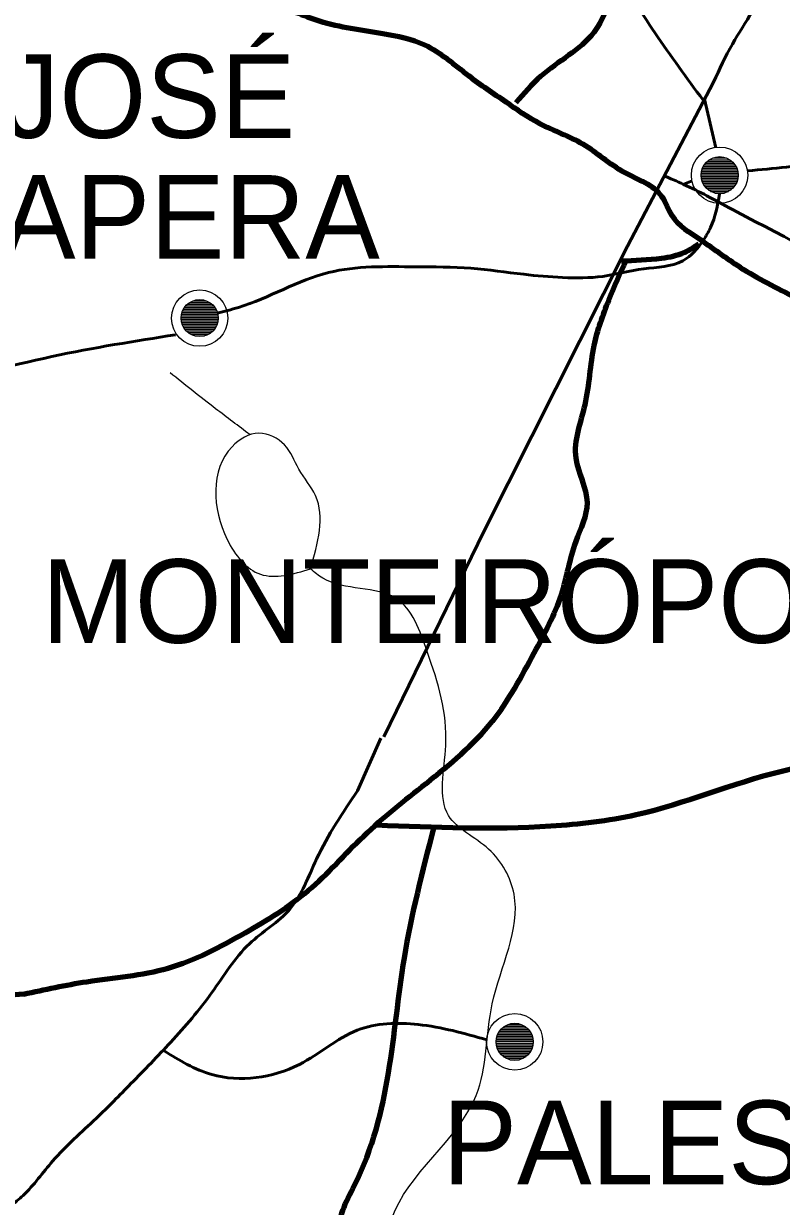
# Model space of a CAD drawing. Extents: x 512883 to 1063249, y 8784064 to 9081064.
# Drawn here: x 674490 to 688095, y 8927073 to 8948300 of the extents above; entities that cross this region are included whole.
import ezdxf

# ---------------------------------------------------------------- set-up
doc = ezdxf.new("R2010")
doc.units = 0
doc.header["$LTSCALE"] = 600
doc.linetypes.add('DOT_DASHED', pattern=[7.7, 5, -1.2, 0.3, -1.2])
for name, color, linetype, lineweight in [('10', 7, 'Continuous', 53), ('13', 7, 'Continuous', 90), ('3', 7, 'Continuous', 25), ('4', 7, 'Continuous', 13), ('5', 7, 'Continuous', 13)]:
    doc.layers.add(name, color=color, linetype=linetype, lineweight=lineweight)

msp = doc.modelspace()

# ---------------------------------------------------------------- linework, layer by layer
at = {"layer": '10'}
for p, q in [((686916.9, 8946073), (686716.2, 8946946.3)), ((686494.2, 8945478.8), (686344.1, 8945417.9)), ((680900.9, 8935478.2), (680484.1, 8934529.4))]:
    msp.add_line(p, q, dxfattribs=at)
msp.add_lwpolyline([(686879, 8947250.2), (685329.9, 8944307.9), (682756.7, 8939198.9), (680955.1, 8935497.3)], dxfattribs=at)
for points in [[(683363, 8951685.3), (684253.4, 8950848.9), (685091, 8949362.2), (685827.1, 8948131.8), (686690.1, 8946927.1)], [(686879, 8947250.2), (687215.3, 8947932.8), (687572, 8948527.5), (687786, 8948956.6), (688076.4, 8949437.6)], [(687492.6, 8945658.8), (688879.6, 8945806.7), (690884.8, 8946191.2), (692737.8, 8946575.7), (694590.7, 8946729.4), (697823.6, 8947505.2)], [(661143.8, 8945556.2), (662407.6, 8946035.8), (663719.6, 8946067.1), (664857.5, 8945518.9), (666015.1, 8944949.5), (668384.9, 8943538.4), (670469.7, 8942009.1), (674994.8, 8942323.4), (677217.8, 8942716)], [(690354.9, 8942526.3), (689817.4, 8943269.9), (687295.1, 8944922.2), (686757.6, 8945211.3), (686340.8, 8945414.9), (685973.5, 8945577)], [(677966.5, 8943105.4), (678346.6, 8943206.6), (679964.3, 8943832.1), (681523.6, 8943935.6), (682522.3, 8943909.7), (683470.1, 8943801.1), (684168.2, 8943744.2), (684886.6, 8943764.9), (685625.5, 8943899.4), (686323.6, 8944044.2), (686695.5, 8944416.5), (686822.9, 8944638.8), (686986.1, 8945247.1)], [(680484.1, 8934529.4), (679750.3, 8933309.1), (679271.3, 8932409.3), (678542.7, 8931783.6), (677870.1, 8930909.7), (677131.2, 8930020.3), (676417.8, 8929275.7), (675796.2, 8928655.1), (675011.5, 8927884.7), (674481.5, 8927269.3), (674252.2, 8927072.8)], [(677011.7, 8929863), (677867, 8929439.7), (679440.8, 8929619.1), (680481.5, 8930234.3), (681572.9, 8930336.8), (682804.7, 8930063.7)]]:
    msp.add_spline(points, degree=3, dxfattribs=at)
at = {"layer": '13'}
for points in [[(687717.5, 8953534.4), (685899.8, 8950515.2), (685172.7, 8949145.3), (684725.3, 8948138.9), (683774.5, 8947356.2), (683327, 8946880.9)], [(697917.7, 8940030.2), (695483.7, 8940642.8), (693475.6, 8941153.4), (692502.1, 8941214.7), (691508.2, 8941480.2), (690352, 8942072.5), (689439.3, 8942726), (688425.1, 8943338.7), (687411, 8943890.1), (686640.2, 8944421.1), (686133.1, 8944850), (685950.6, 8945197.2), (685281.2, 8945626.1), (684530.7, 8946136.7), (683760, 8946504.3), (683151.5, 8946892.3), (682482.1, 8947362.1), (681691.1, 8947913.5), (680940.6, 8948117.7), (679804.7, 8948342.4), (678932.6, 8948669.2), (678381, 8948825.9)], [(674490.5, 8930880.6), (672043.1, 8930925.7), (668845.2, 8932294), (665328.7, 8934774.4), (663896.9, 8936642.6), (661883.5, 8938670.4), (659757.9, 8940179.9), (657908.6, 8942328.8), (656340.6, 8944429.5), (655853.4, 8945212.2), (655718.6, 8945507.2)], [(685224.7, 8944040.7), (685943.8, 8944092.2), (686354.8, 8944195), (686611.6, 8944349.2)], [(674490.5, 8930880.6), (675626.4, 8931105.2), (677086.8, 8931350.3), (678466, 8931983.4), (679601.9, 8932739.1), (680595.8, 8933719.4), (681711.4, 8934658.9), (682908.1, 8935782.1), (683658.6, 8937007.5), (684145.3, 8938049.1), (684409, 8939009), (684611.9, 8939703.4), (684409, 8940499.9), (684571.3, 8941459.8), (684733.6, 8942521.8), (684997.2, 8943338.7), (685312.5, 8944057.4)], [(680828.7, 8933919), (683954.5, 8933899.9), (685486.5, 8934104.2), (688100.7, 8934885), (691225.8, 8935479.3), (693370.2, 8936322.6), (696113.8, 8936977.5)], [(681850.5, 8933861.5), (681321, 8931529.8), (680425, 8927444), (680180.5, 8926536.1), (680282.8, 8926350.2), (680670.9, 8926329), (682182.8, 8925955.3), (684185.2, 8925312.7), (684696.1, 8925126.2), (684982.2, 8924919.4), (685125.4, 8924568.3), (686740.3, 8923038.6), (687253.7, 8921944)]]:
    msp.add_spline(points, degree=3, dxfattribs=at)
at = {"layer": '3', "lineweight": 13}
for points in [[(678553.7, 8940923.5), (677937.3, 8941388.8), (677120.1, 8942034.4)], [(679643.2, 8938512.8), (678742.1, 8938418.6), (678144.9, 8939041.5), (678233.9, 8940707), (678715.6, 8940949.3), (679174.8, 8940739.2), (679432.7, 8940304.7), (679730.3, 8939828.7), (679643.2, 8938512.8)], [(677984.7, 8918570.3), (678406.7, 8920626.1), (679076, 8922265.5), (680680.5, 8922887.9), (681054.8, 8925497.1), (681102.1, 8926854.5), (682615, 8929061.9), (682904, 8930705), (683294.9, 8932676.2), (682838.8, 8933483), (682121.5, 8934086.4), (682068.2, 8935341.9), (681737, 8937032.1), (681181.6, 8937983.8), (679862.5, 8938346.1), (679643.2, 8938512.8)]]:
    msp.add_spline(points, degree=3, dxfattribs=at)
at = {"layer": '3'}
msp.add_spline([(679643.2, 8938512.8), (678742.1, 8938418.6), (678144.9, 8939041.5), (678233.9, 8940707), (678715.6, 8940949.3), (679174.8, 8940739.2), (679432.7, 8940304.7), (679730.3, 8939828.7), (679643.2, 8938512.8)], degree=3, dxfattribs=at)
at = {"layer": '4', "linetype": 'DOT_DASHED', "lineweight": 25}
msp.add_spline([(649305.2, 8929224.6), (649906.8, 8931577.6), (650496.3, 8933626.8), (651745.4, 8937244.4), (650026.3, 8938890.1), (648813.5, 8940627.9), (648150.6, 8942602.8), (647468, 8944598.9), (647078.2, 8946150.5), (647172.8, 8947711.3), (647617.2, 8948659.4), (647803.9, 8950739.1), (648059.7, 8953213.2), (648283, 8955125.2), (648539.5, 8955786.1), (649780.9, 8959049.5), (650736.6, 8960318.9), (652033.8, 8961517.6), (652561.8, 8963526.7), (652858.7, 8964186.5), (654217.2, 8965425.5), (654887, 8966535), (655308.9, 8967379.5), (655992.8, 8969134.7), (656859.3, 8970010.3), (658218.7, 8971290.9), (659592.4, 8972300.3), (660729.1, 8973544.6), (661684.5, 8973876.1), (663627.8, 8975101.2), (664866.2, 8976384.7), (665579.7, 8976722), (666723.4, 8977361.8), (667655.3, 8978465), (668765, 8979397.3), (670276.7, 8980257.5), (670730.7, 8980726), (673194.5, 8982689), (673989.8, 8984003.9), (674145.8, 8985605), (673414.7, 8987227.2), (672983.2, 8988717.2), (672885.3, 8990699.4), (673627, 8992328.2), (674021.8, 8993777.8), (674826.7, 8995530.1), (675940.8, 8997587.7), (677572.3, 9000237.4), (677647.8, 9000923.4), (677610.1, 9001966.4), (678954.8, 9003497.5), (679698.8, 9005230.4), (681172.8, 9006216.6), (682944.3, 9006966.4), (683427.6, 9007851.1), (682741.8, 9009701.4), (681771.4, 9011454.3), (681734.9, 9013476.8), (681996.3, 9015283.8), (682991, 9016489.8)], degree=3, dxfattribs=at)
at = {"layer": '5'}
for p, q in [((686765.2, 8945828.9), (687206.8, 8945828.9)), ((686804.8, 8945858.9), (687167.2, 8945858.9)), ((686862.1, 8945888.9), (687109.9, 8945888.9)), ((686655.7, 8945618.9), (687316.3, 8945618.9)), ((686660.5, 8945648.9), (687311.5, 8945648.9)), ((686668.6, 8945678.9), (687303.4, 8945678.9)), ((686679.4, 8945708.9), (687292.6, 8945709.2)), ((686693.8, 8945738.9), (687278.5, 8945738.9)), ((686712.1, 8945768.9), (687260.2, 8945768.9)), ((686736.1, 8945798.9), (687236.5, 8945798.9)), ((686653.6, 8945588.9), (687318.4, 8945588.9)), ((686654.2, 8945558.9), (687318.1, 8945558.9)), ((686657.2, 8945528.9), (687314.8, 8945528.9)), ((686663.2, 8945498.9), (687308.8, 8945498.9)), ((686672.2, 8945468.9), (687299.8, 8945468.9)), ((686684.8, 8945438.9), (687287.5, 8945439.2)), ((686700.7, 8945408.9), (687271.3, 8945408.9)), ((686721.4, 8945378.9), (687250.9, 8945379.2)), ((686746.6, 8945348.7), (687225.7, 8945348.9)), ((686779.9, 8945318.9), (687192.1, 8945318.9)), ((686824.9, 8945288.9), (687147.1, 8945288.9)), ((686898.7, 8945258.9), (687073, 8945258.9)), ((677469.8, 8943294.1), (677832.2, 8943294.1)), ((677527.1, 8943324.1), (677774.9, 8943324.1)), ((677325.5, 8943084.1), (677976.5, 8943084.1)), ((677333.6, 8943114.1), (677968.4, 8943114.1)), ((677344.4, 8943144.1), (677957.6, 8943144.4)), ((677358.8, 8943174.1), (677943.5, 8943174.1)), ((677377.1, 8943204.1), (677925.2, 8943204.1)), ((677401.1, 8943234.1), (677901.5, 8943234.1)), ((677430.2, 8943264.1), (677871.8, 8943264.1)), ((677318.6, 8943024.1), (677983.4, 8943024.1)), ((677319.2, 8942994.1), (677983.1, 8942994.1)), ((677320.7, 8943054.1), (677981.3, 8943054.1)), ((677322.2, 8942964.1), (677979.8, 8942964.1)), ((677328.2, 8942934.1), (677973.8, 8942934.1)), ((677337.2, 8942904.1), (677964.8, 8942904.1)), ((677349.8, 8942874.1), (677952.5, 8942874.4)), ((677365.7, 8942844.1), (677936.3, 8942844.1)), ((677386.4, 8942814.1), (677915.9, 8942814.4)), ((677411.6, 8942783.8), (677890.7, 8942784.1)), ((677444.9, 8942754.1), (677857.1, 8942754.1)), ((677489.9, 8942724.1), (677812.1, 8942724.1)), ((677563.7, 8942694.1), (677738, 8942694.1)), ((683183.1, 8930334.5), (683430.9, 8930334.5)), ((682989.6, 8930124.5), (683624.4, 8930124.5)), ((683000.4, 8930154.5), (683613.6, 8930154.8)), ((683014.8, 8930184.5), (683599.5, 8930184.5)), ((683033.1, 8930214.5), (683581.2, 8930214.5)), ((683057.1, 8930244.5), (683557.5, 8930244.5)), ((683086.2, 8930274.5), (683527.8, 8930274.5)), ((683125.8, 8930304.5), (683488.2, 8930304.5)), ((682974.6, 8930034.5), (683639.4, 8930034.5)), ((682975.2, 8930004.5), (683639.1, 8930004.5)), ((682976.7, 8930064.5), (683637.3, 8930064.5)), ((682978.2, 8929974.5), (683635.8, 8929974.5)), ((682981.5, 8930094.5), (683632.5, 8930094.5)), ((682984.2, 8929944.5), (683629.8, 8929944.5)), ((682993.2, 8929914.5), (683620.8, 8929914.5)), ((683005.8, 8929884.5), (683608.5, 8929884.8)), ((683021.7, 8929854.5), (683592.3, 8929854.5)), ((683042.4, 8929824.5), (683571.9, 8929824.8)), ((683067.6, 8929794.2), (683546.7, 8929794.5)), ((683100.9, 8929764.5), (683513.1, 8929764.5)), ((683145.9, 8929734.5), (683468.1, 8929734.5)), ((683219.7, 8929704.5), (683394, 8929704.5))]:
    msp.add_line(p, q, dxfattribs=at)
for centre, radius in [((686986.1, 8945579.9), 506.1), ((686986.1, 8945579.9), 332.9), ((677651, 8943015.1), 506.1), ((677651, 8943015.1), 332.9), ((683307.1, 8930025.5), 506.1), ((683307.1, 8930025.5), 332.9)]:
    msp.add_circle(centre, radius, dxfattribs=at)

# ---------------------------------------------------------------- texts
for s, p in [('SÃO JOSÉ', (669335.4, 8946249.6)), ('DA TAPERA', (669516.3, 8944081.7)), ('MONTEIRÓPOLIS', (674815.8, 8937186.6)), ('PALESTINA', (682012.2, 8927470.7))]:
    msp.add_text(s, height=1500, dxfattribs=at).set_placement(p)

doc.saveas('drawing.dxf')
